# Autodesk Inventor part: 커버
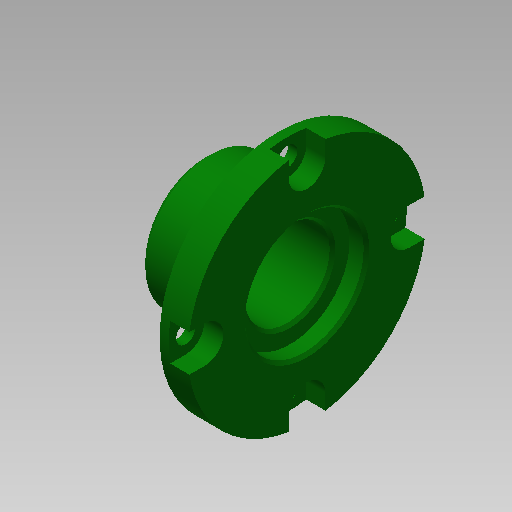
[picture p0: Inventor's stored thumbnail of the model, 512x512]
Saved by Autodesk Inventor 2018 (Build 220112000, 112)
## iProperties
Created: 2019-10
Part Number: 커버
Material: 알루미늄 6061
Document SubType Name: Modeling
Designer: mduedu
Density: 1 g/cm^3
Appearance: 진녹색
Author: mduedu
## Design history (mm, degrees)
sketch "스케치1"
  geometry: L1 (0, 0)-(-18, 0); L2 (-18, 0)-(-18, 11.5); L3 (-18, 11.5)-(-5, 11.5); L4 (-5, 11.5)-(-5, 21); L5 (-5, 21)-(0, 21); L6 (0, 21)-(0, 0)
  constraints: 12 end point, 3 parallel, 2 perpendicular, 1 horizontal
  dimensions: "d0" = 18 distance of L1.start L1.end; "d1" = 42 diameter of L5 L1; "d2" = 23 diameter of L3 L1; "d3" = 13 distance of L2.end L3.end
revolve "회전1" sketch "스케치1" stored, may be unused: angle "d4" = 90 deg
hole "구멍1" diameter "d7" = 15; stored, may be unused: countersink angle "d11" = 90 deg, drill point angle "d13" = 118 deg; dims "d5" = 10, "d6" = 10, "d8" = 6, "d9" = 21, "d10" = 3, "d12" = 8
chamfer "모따기1" distance "d14" = 1; stored, may be unused: second distance "d15" = 2, angle "d16" = 45 deg
sketch "스케치2" dims "d17" = 36
  geometry: 6 further points
  constraints: 2 vertical alignment, 1 coincident, 7 other
  dimensions: "d20" = 360 deg dimension on point (0, 0) point (0, 18) (derived)
sketch "스케치3"
  geometry: 4 further points
  constraints: 4 other
hole "구멍2" sketch "스케치3" at (-18, 0), (0, -18), (18, 0), (0, 18) diameter "d22" = 3.4; stored, may be unused: countersink angle "d26" = 90 deg, drill point angle "d28" = 0 deg; dims "d23" = 6, "d24" = 6.5, "d25" = 3.4, "d27" = 8
sketch "스케치4"
  geometry: L1 (-21.25, 20.747)-(-21.25, 18); L2 (-14.75, 18)-(-14.75, 20.747); A1 r 3.25 centre (-18, 18) between (-19.349, 20.957) and (-16.651, 20.957) reference; A2 r 21 centre (-18, 0) between (-19.349, 20.957) and (-38.957, 1.349) reference; A3 r 21 centre (-18, 0) between (2.957, 1.349) and (-16.651, 20.957) reference; A4 r 21 centre (-18, 0) between (-14.75, 20.747) and (-21.25, 20.747); A5 r 3.25 centre (-18, 18) between (-21.25, 18) and (-14.75, 18); 1 further point
  constraints: 8 point on circle, 4 end point, 2 centre point, 2 coincident, 2 tangent, 1 parallel, 1 vertical
extrude "돌출1" cut sketch "스케치4" stored distance "d29" = 10; taper "d30" = 0 deg
chamfer "모따기3" distance "d37" = 0.5; stored, may be unused: second distance "d38" = 2, angle "d39" = 45 deg
chamfer "모따기4" distance "d40" = 0.5; stored, may be unused: second distance "d41" = 2, angle "d42" = 45 deg
node "솔리드1"
pattern_circular "원형 패턴1" dims angle "d32" = 360 deg
